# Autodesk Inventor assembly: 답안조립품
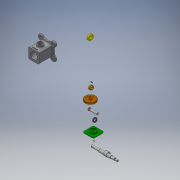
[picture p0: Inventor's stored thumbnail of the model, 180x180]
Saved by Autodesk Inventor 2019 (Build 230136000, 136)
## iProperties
Created: 2021-01
Part Number: 답안조립품
Material: 일반
Document SubType Name: Assembly
Designer: 3dpro14
Author: 3dpro14
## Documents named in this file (11)
- C:\Users\3dpro14\Desktop\710114V1009\답안조립품.iam
- C:\Users\3dpro14\Desktop\710114V1009\본체.ipt
- C:\Users\3dpro14\Desktop\710114V1009\베어링 6203.ipt
- C:\Users\3dpro14\Desktop\710114V1009\볼트 M4.ipt
- C:\Users\3dpro14\Desktop\710114V1009\부시.ipt
- C:\Users\3dpro14\Desktop\710114V1009\스퍼기어.ipt
- C:\Users\3dpro14\Desktop\710114V1009\슬라이더.ipt
- C:\Users\3dpro14\Desktop\710114V1009\오일 실.ipt
- C:\Users\3dpro14\Desktop\710114V1009\커버.ipt
- C:\Users\3dpro14\Desktop\710114V1009\키 4 x 4 x 14.ipt
- C:\Users\3dpro14\Desktop\710114V1009\편심축.ipt
